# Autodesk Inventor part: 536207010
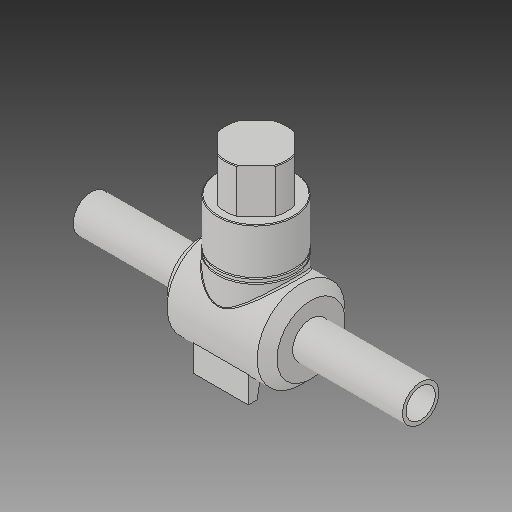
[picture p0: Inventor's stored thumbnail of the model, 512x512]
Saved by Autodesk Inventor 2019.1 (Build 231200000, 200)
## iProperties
Created: 2017-08
Part Number: 536207010
Material: Generic
Description: PLASSON PE BALL VALVE 1IPS''
Document SubType Name: Modeling
Designer: Кирилл
Density: 1 g/cm^3
Appearance: Default
Author: Кирилл
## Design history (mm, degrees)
derived "536207.ipt"
feature "Solid1::536207.ipt"
feature "Solid2::536207.ipt"
tag "TaggingFeature1"
body "Solid1"
other parameters: "d1" = 33.3, "d5" = 24.975, "d6" = 9, "d11" = 56, "d12" = 0.7, "d13" = 4, "d14" = 4, "d16" = 100 deg, "d19" = 48, "d21" = 0, "d22" = 0.7, "d26" = 3.3, "d28" = 0, "d29" = 1.4, "d32" = 64, "d33" = 47.8, "d37" = 0, "d_" = 33.3, "s_" = 3.3, "H_1" = 48, "A_" = 64, "C_" = 47.8, "dp" = 24, "D_" = 26.6, "U_" = 26
